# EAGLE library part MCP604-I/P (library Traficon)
OP AMP
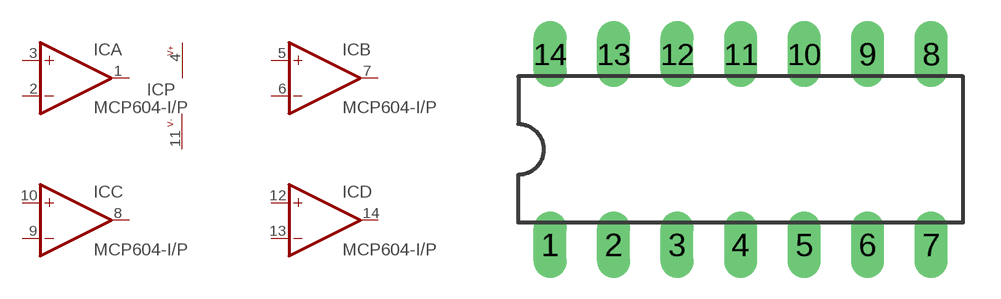
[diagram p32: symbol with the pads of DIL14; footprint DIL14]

Designator prefix IC; gates A=OPAMP B=OPAMP C=OPAMP D=OPAMP P=PWR+-

## MCP604-I/PP  [DIL14]
1  A:OUT  out
2  A:-IN  in
3  A:+IN  in
4  P:V+  pas
5  B:+IN  in
6  B:-IN  in
7  B:OUT  out
8  C:OUT  out
9  C:-IN  in
10  C:+IN  in
11  P:V-  pas
12  D:+IN  in
13  D:-IN  in
14  D:OUT  out

## Footprint DIL14 (pad centres in mm)
Dual In Line Package
drill 0.813 long: 1 -7.62,-3.81; 2 -5.08,-3.81; 3 -2.54,-3.81; 4 0,-3.81; 5 2.54,-3.81; 6 5.08,-3.81; 7 7.62,-3.81; 8 7.62,3.81; 9 5.08,3.81; 10 2.54,3.81; 11 0,3.81; 12 -2.54,3.81; 13 -5.08,3.81; 14 -7.62,3.81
